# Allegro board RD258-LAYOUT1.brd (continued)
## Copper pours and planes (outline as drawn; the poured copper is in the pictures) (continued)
SIG00063 on TOP: 29.15,56.2 29.02,56.23 28.93,56.33 28.9,56.45 28.9,56.71 28.52,57.63 27.6,58.01 26.94,58.01 26.82,58.04 26.73,58.13 26.69,58.26 26.69,60.9 26.69,60.97 26.72,61.02 27.17,61.47 27.2,61.49 27.24,61.5 33.8,61.5 33.91,61.46 33.95,61.35 33.95,58.5 33.91,58.39 33.8,58.35 30.96,58.35 30.79,58.32 30.64,58.22 30.22,57.79 30.16,57.72 30.1,57.6 30.1,56.49 30.09,56.45 30.07,56.42 29.88,56.23 29.85,56.21 29.81,56.2
SIG00065 on TOP: 34.4,54.4 34.33,54.43 34.3,54.5 34.3,58.54 34.34,58.64 34.56,58.86 34.6,58.96 34.6,61.09 34.64,61.19 35.11,61.66 35.15,61.76 35.15,63.2 35.19,63.31 35.3,63.35 37.11,63.35 37.15,63.34 37.18,63.32 37.6,62.9 37.62,62.87 37.62,62.83 37.62,54.69 37.58,54.58 37.43,54.43 37.4,54.41 37.36,54.4
SIG00065 on BOTTOM: 34.45,52.95 34.38,52.98 34.35,53.05 34.35,58.25 34.38,58.32 34.45,58.35 36.84,58.35 36.94,58.31 37.47,57.78 37.49,57.75 37.5,57.71 37.5,54.19 37.49,54.15 37.47,54.12 36.34,52.99 36.24,52.95
SIG00065 on CONDUCTIVE3: 39.1,52.71 39.07,52.84 39.03,52.89 37.75,54.17 35.75,54.17 35.62,54.2 35.53,54.29 35.5,54.42 35.5,57.15 35.49,57.21 35.47,57.27 35.47,57.42 35.6,57.5 40.49,57.5 40.55,57.49 40.59,57.46 41.96,56.09 41.99,56.05 42,55.99 42,30.2 41.99,30.14 41.93,30.03 39.29,27.39 39.25,27.36 39.19,27.35 33.91,27.35 33.85,27.36 33.81,27.39 33.24,27.96 33.21,28 33.2,28.06 33.2,29.21 33.21,29.27 33.27,29.39 34.22,30.33 34.27,30.36 34.32,30.38 38.45,30.38 38.57,30.41 38.62,30.45 39.98,31.8 40.04,31.91 40.05,31.98 40.05,48.12 39.99,48.41 39.83,48.65 39.25,49.23 39.21,49.27 39.16,49.3 39.12,49.36 39.1,49.42 39.1,51 ; 3 cut-outs
SIG00071 on TOP: 26.95,44.6 26.82,44.63 26.73,44.73 26.7,44.85 26.7,47.16 26.73,47.28 26.82,47.38 26.95,47.41 27.6,47.41 28.52,47.79 28.9,48.71 28.9,49.15 28.93,49.27 29.02,49.37 29.15,49.4 32.35,49.4 32.48,49.37 32.57,49.27 32.6,49.15 32.6,47 32.59,46.94 32.53,46.83 31.82,46.12 31.76,46.01 31.75,45.95 31.75,44.7 31.72,44.63 31.65,44.6
SIG00079 on TOP: 8.23,54.39 8.19,54.39 8.16,54.42 8.01,54.57 7.76,54.71 7.62,54.73 6.25,54.73 6.18,54.76 6.15,54.83 6.15,59 6.18,59.12 6.28,59.22 6.4,59.25 9.27,59.25 9.4,59.22 9.49,59.12 9.52,59 9.52,54.64 9.49,54.51 9.4,54.42 9.27,54.39
SIG00079 on BOTTOM: 8.68,54.38 8.61,54.38 8.5,54.45 7.95,55 6.8,55 6.71,55.02 6.63,55.07 6.47,55.23 6.42,55.31 6.4,55.4 6.4,56.55 6.38,56.64 6.33,56.72 6.22,56.83 6.14,56.88 6.05,56.9 4.85,56.9 4.78,56.93 4.75,57 4.75,58.8 4.76,58.86 4.82,58.97 5.03,59.18 5.08,59.22 5.2,59.25 8.92,59.25 8.99,59.24 9.1,59.18 9.46,58.82 9.49,58.77 9.53,58.65 9.53,55.3 9.53,55.29 9.53,54.48 9.5,54.4 9.43,54.38
VE_A on TOP: outline of 208 points within 50,21.95 70.5,66 ; 5 cut-outs
VE_A on BOTTOM: 65.62,57.59 64.7,57.21 64.32,56.29 64.32,56.22 64.33,56.13 64.33,54.2 64.32,54.11 64.32,54.03 64.32,50.5 64.33,50.36 64.36,50.23 64.36,50.19 64.35,50.15 64.35,48.56 64.34,48.54 64.33,48.42 64.32,48.29 64.99,47.15 66.32,47.19 66.34,47.21 66.45,47.22 66.5,47.13 66.5,41.68 66.5,41.66 66.5,36.26 66.49,36.23 66.48,36.2 66.48,27.7 66.49,27.67 66.53,27.65 70.4,27.65 70.47,27.62 70.5,27.55 70.5,23.95 69.91,22.54 68.5,21.95 52,21.95 50.59,22.54 50,23.95 50,65.9 50.03,65.97 50.1,66 70.4,66 70.47,65.97 70.5,65.9 70.5,60.39 70.47,60.32 70.4,60.29 66.55,60.29 66.51,60.28 66.5,60.24 66.5,57.84 66.47,57.72 66.38,57.62 66.25,57.59 ; 11 cut-outs
VE_A on CONDUCTIVE2: 65.85,51.99 65.81,51.88 65.7,51.84 65.62,51.84 64.7,51.46 64.32,50.54 64.32,48.29 64.7,47.37 65.62,46.99 66.25,46.99 66.38,46.96 66.47,46.87 66.5,46.74 66.5,41.68 66.5,41.66 66.5,35.46 66.5,35.44 66.5,27.7 66.51,27.67 66.55,27.65 70.35,27.65 70.46,27.61 70.5,27.5 70.5,23.95 69.91,22.54 68.5,21.95 52,21.95 50.59,22.54 50,23.95 50,65.85 50.04,65.96 50.15,66 70.35,66 70.46,65.96 70.5,65.85 70.5,60.44 70.46,60.33 70.35,60.29 66.55,60.29 66.51,60.28 66.5,60.24 66.5,57.84 66.47,57.72 66.38,57.62 66.25,57.59 65.62,57.59 64.7,57.21 64.32,56.29 64.32,54.04 64.7,53.12 65.62,52.74 65.7,52.74 65.81,52.7 65.85,52.59 ; 16 cut-outs
VE_A on CONDUCTIVE3: 66.51,27.67 66.55,27.65 70.35,27.65 70.46,27.61 70.5,27.5 70.5,23.95 69.91,22.54 68.5,21.95 52,21.95 50.59,22.54 50,23.95 50,65.85 50.04,65.96 50.15,66 70.35,66 70.46,65.96 70.5,65.85 70.5,60.44 70.46,60.33 70.35,60.29 66.55,60.29 66.51,60.28 66.5,60.24 66.5,57.84 66.47,57.72 66.38,57.62 66.25,57.59 65.62,57.59 64.7,57.21 64.32,56.29 64.32,56.29 64.32,54.04 64.71,53.11 65.64,52.74 65.75,52.7 65.79,52.59 65.79,51.99 65.75,51.88 65.64,51.84 65.62,51.84 64.76,51.51 64.33,50.69 64.33,48.45 64.33,48.43 64.65,47.42 65.62,46.99 66.25,46.99 66.38,46.96 66.47,46.87 66.5,46.74 66.5,41.68 66.5,41.66 66.5,35.46 66.5,35.44 66.5,27.7 ; 1 cut-out
VE_B on TOP: outline of 187 points within 22.7,21.95 43,66 ; 7 cut-outs
VE_B on TOP: 28.4,32 28.29,32.04 28.25,32.15 28.25,33.16 28.23,33.24 28.17,33.31 28.16,33.33 28.09,33.38 28,33.41 26.83,33.41 26.79,33.41 26.76,33.44 26.72,33.49 26.7,33.55 26.7,33.57 26.7,33.9 26.7,33.93 26.7,35.8 26.74,35.9 26.85,35.95 27.93,35.95 28.04,35.9 28.08,35.8 28.08,35.5 28.08,35.49 28.21,35.03 28.65,34.85 29.25,34.85 29.34,34.83 29.42,34.79 29.44,34.75 29.45,34.71 29.45,34.7 29.46,34.62 29.5,34.52 29.5,34.49 29.5,34.1 29.55,33.97 29.67,33.9 29.7,33.89 29.73,33.87 29.93,33.67 29.97,33.62 30,33.5 30,32.4 29.97,32.33 29.76,32.24 29.67,32.03 29.6,32
VE_B on BOTTOM: 22.7,65.9 22.73,65.97 22.8,66 42.9,66 42.97,65.97 43,65.9 43,23.95 42.41,22.54 41,21.95 24.7,21.95 23.29,22.54 22.7,23.95 22.7,27.55 22.73,27.62 22.8,27.65 26.65,27.65 26.69,27.66 26.7,27.7 26.7,39.22 26.7,39.25 26.7,44.95 26.69,44.97 26.69,47.06 26.7,47.1 26.72,47.13 26.97,47.38 27.01,47.4 27.04,47.41 27.6,47.41 28.52,47.79 28.9,48.71 28.9,56.45 28.89,56.48 28.89,56.51 28.28,57.82 26.85,57.77 26.75,57.77 26.69,57.85 26.69,60.66 26.68,60.7 26.64,60.71 22.8,60.71 22.73,60.74 22.7,60.81 ; 9 cut-outs
VE_B on CONDUCTIVE3: 26.69,35.49 26.7,35.52 26.7,41.72 26.69,41.76 26.69,47.26 26.74,47.37 26.84,47.41 27.6,47.41 28.52,47.79 28.9,48.71 28.9,51 28.9,51.01 28.53,51.87 27.69,52.26 27.59,52.3 27.55,52.41 27.55,53.01 27.59,53.12 27.69,53.16 28.56,53.58 28.9,54.49 28.9,54.5 28.9,56.65 28.9,56.71 28.52,57.63 27.6,58.01 26.84,58.01 26.74,58.05 26.69,58.16 26.69,60.66 26.68,60.7 26.64,60.71 22.85,60.71 22.74,60.75 22.7,60.86 22.7,65.85 22.74,65.96 22.85,66 42.85,66 42.96,65.96 43,65.85 43,23.95 42.41,22.54 41,21.95 24.7,21.95 23.29,22.54 22.7,23.95 22.7,27.5 22.74,27.61 22.85,27.65 26.65,27.65 26.69,27.66 26.7,27.7 26.7,33.9 26.69,33.95 ; 4 cut-outs
VL_A on TOP: outline of 82 points within 54.96,29.55 62.75,41.45 ; 1 cut-out
VL_B on TOP: 31.3,31.75 31.23,31.78 31.2,31.85 31.2,33.8 31.23,33.87 31.3,33.9 31.4,33.9 31.54,33.96 31.6,34.1 31.6,34.6 31.61,34.66 31.67,34.77 32.27,35.37 32.3,35.39 32.34,35.4 32.75,35.87 32.3,36.3 32.26,36.31 32.22,36.33 31.92,36.63 31.88,36.68 31.85,36.81 31.85,38.76 31.88,38.9 31.9,39.01 31.72,39.54 31.22,39.8 31.2,39.8 30.35,39.8 30.28,39.83 30.25,39.9 30.25,40.5 30.26,40.57 30.32,40.68 30.47,40.83 30.5,40.85 30.54,40.85 33.2,40.85 33.24,40.85 33.27,40.83 34.16,39.94 34.2,39.89 34.23,39.77 34.23,34.93 34.22,34.87 34.16,34.76 32.52,33.12 32.46,33.01 32.45,32.95 32.45,32 32.42,31.88 32.33,31.78 32.2,31.75

Small or netless copper shapes (teardrops, artwork), in the pictures only: 43 on TOP, 50 on BOTTOM, 6 on CONDUCTIVE3, 1 on CONDUCTIVE2

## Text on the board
Ref Des/Silkscreen Bottom: C60 | R59 | R58 | R18 | C16 | R20 | C150 | C149 | R19 | C53 | R46 | D19 | R47 | R62 | R63 | C64 | Q4 | C65 | R107 | D5 | C22 | D6 | R41 | R42 | D14 | C6 | R2 | R187 | R25 | R26 | C32 | C33 | D25 | R8 | D24 | R188 | C5 | R3 | R1 | Q6 | R50 | R60 | C61 | D18 | R15 | D21 | R45 | C55 | Q3 | IC25 | C18 | C200 | R174 | D7 | CN3 | R16 | Q1 | CN2 | R149 | C7 | C8 | C36 | IC26 | R24 | D10 | D13 | C4 | C42
Ref Des/Silkscreen Top: C62 | C63 | C17 | R17 | C19 | C20 | R61 | R57 | TP4 | IC22 | C147 | C148 | C146 | IC10 | T2 | R6 | R7 | IC13 | TP8 | R64 | D23 | R186 | C52 | C51 | D17 | C50 | D22 | C68 | CN1 | C31 | C34 | D11 | D9 | D15 | C45 | C46 | C49 | R43 | R23 | R141 | IC9 | R9 | T1 | R10 | IC6 | IC21 | IC27 | C15 | C14 | C13 | IC8 | C26 | R11 | C43 | C44 | C2 | C1 | TP3 | R36 | R40 | TP1 | R37 | R53 | IC20 | IC5 | C21 | C29 | TP38 | C30 | IC12 | TP7 | IC28 | C12 | C11 | R14 | R4 | D3 | D4 | R170 | C145 | C27 | TP6 | R44 | R166 | Q32 | C125 | R185 | Q26 | R145 | C23 | D2 | D1 | R12 | R13 | C10 | C9 | C3 | R5 | TP13 | C25 | IC1 | Q2 | R29 | IC16 | R38 | R32 | C41 | R39 | Q5
SYMBOL-1-TOP: 9 | 1 | 2 | 10 | RD258-1
SYMBOL-1-BOTTOM: 5 | 2 | 1 | 4 | 13 | 12 | 15 | 14 | 9 | 10
